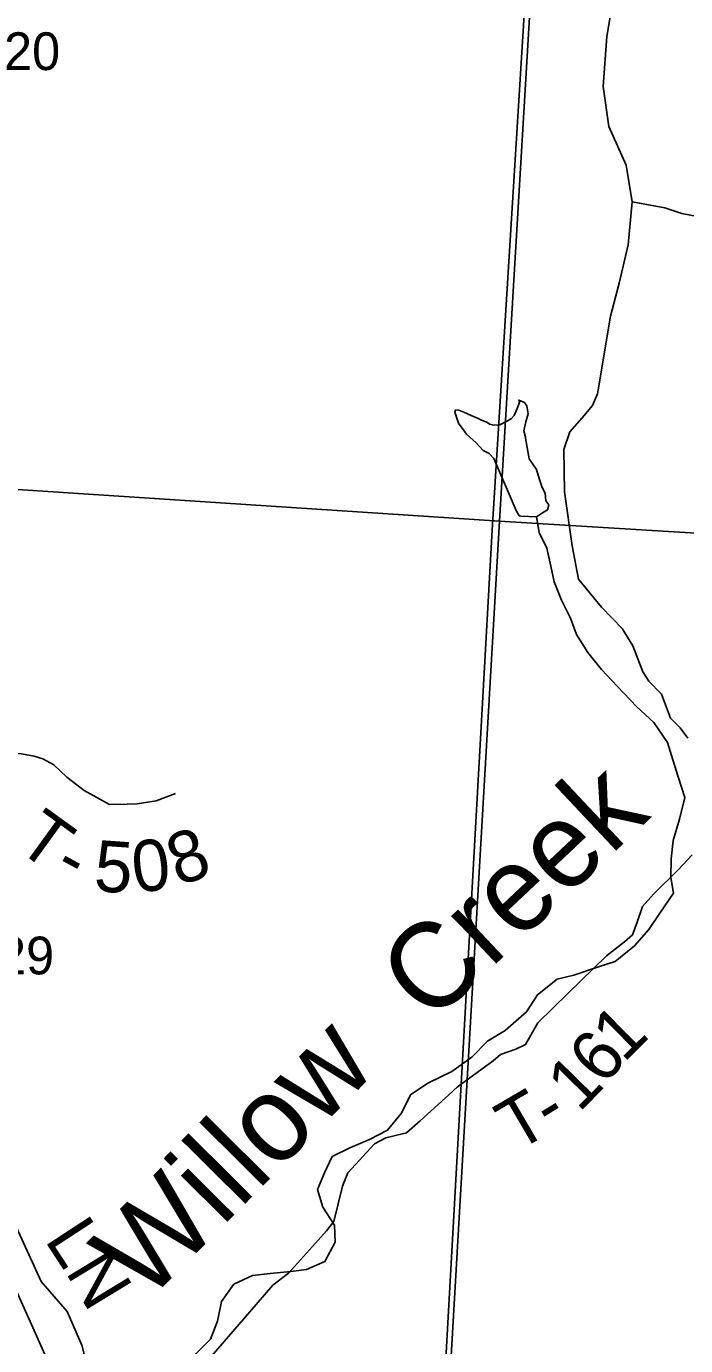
# Model space of a CAD drawing. Extents: x 1949938.81 to 1949945.61, y 152207.65 to 152214.09.
# Drawn here: x 1949940.868 to 1949941.599, y 152210.308 to 152211.771 of the extents above; entities that cross this region are included whole.
import ezdxf

# ---------------------------------------------------------------- set-up
doc = ezdxf.new("R2010")
doc.units = 0
for name, color, linetype in [('GM_X_County_Road', 7, 'Continuous'), ('GM_X_County_Road_Text', 7, 'Continuous'), ('GM_X_Minor_Lake', 7, 'Continuous'), ('GM_X_Minor_River', 7, 'Continuous'), ('GM_X_Minor_River_Text', 7, 'Continuous'), ('GM_X_Section', 7, 'Continuous'), ('GM_X_Section_Text', 7, 'Continuous'), ('GM_X_Township', 7, 'Continuous'), ('GM_X_Township_Road', 7, 'Continuous'), ('GM_X_Township_Road_Text', 7, 'Continuous'), ('GM_X_US_Route', 7, 'Continuous')]:
    doc.layers.add(name, color=color, linetype=linetype)

msp = doc.modelspace()

# ---------------------------------------------------------------- linework, layer by layer
at = {"layer": 'GM_X_County_Road'}
msp.add_lwpolyline([(1949940.6238, 152210.9905), (1949940.7663, 152210.6357), (1949940.884, 152210.3789), (1949940.9129, 152210.3457), (1949940.9292, 152210.3083), (1949940.9485, 152210.2329)], dxfattribs=at)
at = {"layer": 'GM_X_Minor_Lake'}
for points in [[(1949941.4217, 152211.3158), (1949941.4198, 152211.3227), (1949941.4221, 152211.3329), (1949941.4247, 152211.3416), (1949941.4232, 152211.3504), (1949941.4206, 152211.3542), (1949941.4141, 152211.3568), (1949941.4149, 152211.3542), (1949941.4122, 152211.3477), (1949941.4092, 152211.3398), (1949941.4058, 152211.336), (1949941.4017, 152211.3337), (1949941.3933, 152211.3295), (1949941.3865, 152211.3292), (1949941.3816, 152211.3303), (1949941.3793, 152211.3318), (1949941.3729, 152211.3345), (1949941.3684, 152211.3368), (1949941.3612, 152211.3398), (1949941.3533, 152211.3436), (1949941.3476, 152211.3456), (1949941.3438, 152211.3459), (1949941.3431, 152211.3433), (1949941.3442, 152211.3402), (1949941.3472, 152211.3311), (1949941.3563, 152211.319), (1949941.3669, 152211.3095), (1949941.3748, 152211.3011), (1949941.3812, 152211.2977), (1949941.3865, 152211.292), (1949941.4114, 152211.2342), (1949941.4144, 152211.2285), (1949941.4163, 152211.2282), (1949941.434, 152211.2275)], [(1949941.434, 152211.2275), (1949941.4405, 152211.2319), (1949941.4462, 152211.235), (1949941.4474, 152211.2406), (1949941.4443, 152211.2452), (1949941.4436, 152211.2536), (1949941.4402, 152211.26), (1949941.4368, 152211.2699), (1949941.4338, 152211.2798), (1949941.4258, 152211.2915), (1949941.4213, 152211.317), (1949941.4217, 152211.3158)]]:
    msp.add_lwpolyline(points, dxfattribs=at)
at = {"layer": 'GM_X_Minor_River'}
msp.add_lwpolyline([(1949941.434, 152211.2275), (1949941.4369, 152211.21), (1949941.4452, 152211.1925), (1949941.4497, 152211.1727), (1949941.4534, 152211.1552), (1949941.4616, 152211.1347), (1949941.4714, 152211.1149), (1949941.4781, 152211.0966), (1949941.4909, 152211.0768), (1949941.506, 152211.0578), (1949941.5234, 152211.0395), (1949941.5452, 152211.0166), (1949941.5641, 152210.999), (1949941.5791, 152210.9769), (1949941.5851, 152210.9579), (1949941.5911, 152210.9389), (1949941.5986, 152210.9161), (1949941.5924, 152210.8918), (1949941.5855, 152210.8682), (1949941.5832, 152210.8477), (1949941.5831, 152210.8272), (1949941.586, 152210.8097), (1949941.5708, 152210.7877), (1949941.5586, 152210.7695), (1949941.5426, 152210.7513), (1949941.5213, 152210.7339), (1949941.5039, 152210.7286), (1949941.4751, 152210.7189), (1949941.4569, 152210.7144), (1949941.4349, 152210.697), (1949941.4227, 152210.678), (1949941.3991, 152210.6576), (1949941.3794, 152210.6455), (1949941.3619, 152210.628), (1949941.3398, 152210.6121), (1949941.314, 152210.5993), (1949941.2943, 152210.5865), (1949941.2836, 152210.5652), (1949941.2684, 152210.547), (1949941.2486, 152210.5364), (1949941.2266, 152210.5274), (1949941.2069, 152210.5176), (1949941.1985, 152210.4994), (1949941.1909, 152210.4811), (1949941.1968, 152210.4614), (1949941.2096, 152210.4415), (1949941.2103, 152210.4225), (1949941.1989, 152210.4013), (1949941.1784, 152210.3922), (1949941.161, 152210.39), (1949941.1382, 152210.3878), (1949941.1185, 152210.3856), (1949941.098, 152210.3758), (1949941.0843, 152210.3568), (1949941.0797, 152210.3348), (1949941.072, 152210.315), (1949941.053, 152210.2961)], dxfattribs=at)
at = {"layer": 'GM_X_Section'}
for points in [[(1949940.3609, 152212.2864), (1949941.4524, 152212.2232), (1949941.3926, 152211.2226), (1949940.2943, 152211.2945)], [(1949941.4524, 152212.2232), (1949942.5545, 152212.1539), (1949942.4891, 152211.1555), (1949941.3926, 152211.2226)], [(1949941.3926, 152211.2226), (1949941.3344, 152210.2133), (1949940.227, 152210.2792), (1949940.2943, 152211.2945)], [(1949942.4891, 152211.1555), (1949942.4221, 152210.1447), (1949941.3344, 152210.2133), (1949941.3926, 152211.2226)]]:
    msp.add_lwpolyline(points, close=True, dxfattribs=at)
at = {"layer": 'GM_X_Township'}
for points in [[(1949941.4472, 152212.2194), (1949941.3847, 152211.2124), (1949941.3503, 152210.5979), (1949941.3284, 152210.2069), (1949941.2927, 152209.598), (1949941.3013, 152209.5538), (1949941.2985, 152209.5306), (1949941.2971, 152209.4892), (1949941.293, 152209.4279), (1949941.2903, 152209.3782), (1949941.2899, 152209.3706), (1949941.286, 152209.2993), (1949941.2812, 152209.1802), (1949941.2628, 152209.0777)], [(1949941.2628, 152209.0777), (1949941.2812, 152209.1802), (1949941.286, 152209.2993), (1949941.2899, 152209.3706), (1949941.2903, 152209.3782), (1949941.293, 152209.4279), (1949941.2971, 152209.4892), (1949941.2985, 152209.5306), (1949941.3013, 152209.5538), (1949941.2927, 152209.598), (1949941.3284, 152210.2069), (1949941.3503, 152210.5979), (1949941.3847, 152211.2124), (1949941.4472, 152212.2194)]]:
    msp.add_lwpolyline(points, dxfattribs=at)
at = {"layer": 'GM_X_Township_Road'}
for points in [[(1949941.54, 152211.5769), (1949941.5332, 152211.6176), (1949941.5142, 152211.6605), (1949941.5078, 152211.7049), (1949941.512, 152211.7604), (1949941.5165, 152211.7866), (1949941.5328, 152211.8348), (1949941.5423, 152211.8936), (1949941.5521, 152211.9688), (1949941.562, 152212.0364), (1949941.5757, 152212.0831), (1949941.5889, 152212.1236), (1949941.598, 152212.1524), (1949941.5935, 152212.1981), (1949941.5893, 152212.2102), (1949941.5858, 152212.2202), (1949941.5857, 152212.2205)], [(1949941.6017, 152210.9816), (1949941.5933, 152210.9934), (1949941.5827, 152211.004), (1949941.5725, 152211.0306), (1949941.5585, 152211.0451), (1949941.5517, 152211.0553), (1949941.5407, 152211.0842), (1949941.5289, 152211.1036), (1949941.5058, 152211.1272), (1949941.4805, 152211.158), (1949941.4733, 152211.1952), (1949941.4649, 152211.2552), (1949941.4642, 152211.302), (1949941.471, 152211.3217), (1949941.4846, 152211.3373), (1949941.496, 152211.3509), (1949941.5017, 152211.3639), (1949941.5161, 152211.4501), (1949941.5256, 152211.4865), (1949941.5354, 152211.5291), (1949941.54, 152211.5769)], [(1949941.965, 152211.4296), (1949941.9509, 152211.4578), (1949941.9272, 152211.491), (1949941.9035, 152211.5147), (1949941.8782, 152211.5273), (1949941.8608, 152211.5258), (1949941.8482, 152211.5258), (1949941.8324, 152211.5305), (1949941.8181, 152211.5384), (1949941.796, 152211.5495), (1949941.7723, 152211.5542), (1949941.7502, 152211.5542), (1949941.7249, 152211.5511), (1949941.7012, 152211.5479), (1949941.6585, 152211.5479), (1949941.638, 152211.5542), (1949941.6127, 152211.5605), (1949941.5953, 152211.5637), (1949941.5763, 152211.57), (1949941.54, 152211.5769)], [(1949940.7369, 152210.9691), (1949940.7456, 152210.9681), (1949940.7827, 152210.969), (1949940.8017, 152210.9656), (1949940.8103, 152210.9621), (1949940.8382, 152210.9649), (1949940.862, 152210.9642), (1949940.8762, 152210.9618), (1949940.8859, 152210.9587), (1949940.8979, 152210.9521), (1949940.9124, 152210.9386), (1949940.9317, 152210.9238), (1949940.96, 152210.9083), (1949940.9794, 152210.9086), (1949940.9904, 152210.909), (1949941.0118, 152210.9124), (1949941.0332, 152210.9203)], [(1949941.3405, 152210.5899), (1949941.342, 152210.5912), (1949941.3456, 152210.5944), (1949941.3503, 152210.5979), (1949941.3857, 152210.6237), (1949941.394, 152210.6309), (1949941.4107, 152210.6366), (1949941.4217, 152210.6419), (1949941.4353, 152210.6658), (1949941.4687, 152210.6985), (1949941.5115, 152210.7403), (1949941.5316, 152210.7559), (1949941.5403, 152210.7635), (1949941.5456, 152210.7775), (1949941.5516, 152210.795), (1949941.5638, 152210.8087), (1949941.591, 152210.8357), (1949941.6066, 152210.8524)], [(1949940.9485, 152210.2329), (1949940.9773, 152210.2129), (1949940.9902, 152210.2163), (1949941.0103, 152210.233), (1949941.0683, 152210.2904), (1949941.1156, 152210.3451), (1949941.141, 152210.3748), (1949941.1584, 152210.3881), (1949941.1853, 152210.4177), (1949941.2008, 152210.4352), (1949941.2088, 152210.4455), (1949941.2186, 152210.4846), (1949941.2243, 152210.4994), (1949941.2539, 152210.5317), (1949941.2664, 152210.5382), (1949941.2895, 152210.5439), (1949941.3046, 152210.5572), (1949941.3405, 152210.5899)]]:
    msp.add_lwpolyline(points, dxfattribs=at)
at = {"layer": 'GM_X_US_Route'}
msp.add_lwpolyline([(1949940.448, 152211.375), (1949940.4583, 152211.3469), (1949940.5043, 152211.2261), (1949940.5628, 152211.0708), (1949940.5921, 152210.9937), (1949940.6917, 152210.7462), (1949940.7773, 152210.5432), (1949940.8719, 152210.3344), (1949940.9687, 152210.1169), (1949941.0372, 152209.9608), (1949941.0687, 152209.891)], dxfattribs=at)

# ---------------------------------------------------------------- texts
at = {"layer": 'GM_X_County_Road_Text'}
for s, rotation, p in [('L', 303.1568, (1949940.8871, 152210.4251)), ('N', 301.3202, (1949940.9101, 152210.3899))]:
    msp.add_text(s, height=0.0568, rotation=rotation, dxfattribs=at).set_placement(p)
at = {"layer": 'GM_X_Minor_River_Text'}
for s, height, rotation, p in [('Creek', 0.09474, 43.2807, (1949941.3161, 152210.6629)), ('Willow', 0.09475, 45.243, (1949941.0005, 152210.3542))]:
    msp.add_text(s, height=height, rotation=rotation, dxfattribs=at).set_placement(p)
at = {"layer": 'GM_X_Section_Text'}
for s, p in [('20', (1949940.8428, 152211.723)), ('29', (1949940.8361, 152210.7197))]:
    msp.add_text(s, height=0.04186, rotation=0, dxfattribs=at).set_placement(p)
at = {"layer": 'GM_X_Township_Road_Text'}
for s, rotation, p in [('T', 324.1291, (1949940.8546, 152210.8599)), ('5', 355.928, (1949940.9415, 152210.8123)), ('0', 6.5317, (1949940.9879, 152210.8101)), ('8', 19.4314, (1949941.0362, 152210.8172)), ('-', 331.6167, (1949940.8959, 152210.8307)), ('1', 44.7226, (1949941.5305, 152210.6209)), ('6', 50.8232, (1949941.5094, 152210.595)), ('1', 45.5093, (1949941.4811, 152210.5657)), ('T', 30.3684, (1949941.4117, 152210.522)), ('-', 31.626, (1949941.4495, 152210.5442))]:
    msp.add_text(s, height=0.0568, rotation=rotation, dxfattribs=at).set_placement(p)

doc.saveas('drawing.dxf')
